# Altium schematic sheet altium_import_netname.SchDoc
size A4
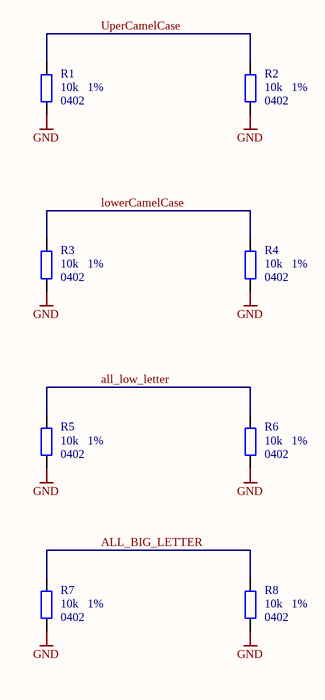
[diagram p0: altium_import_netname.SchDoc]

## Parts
R1  tolerance: 1%  package: 0402  [CRCW0402]  (hidden comment: 10k)
R2  tolerance: 1%  package: 0402  [CRCW0402]  (hidden comment: 10k)
R3  tolerance: 1%  package: 0402  [CRCW0402]  (hidden comment: 10k)
R4  tolerance: 1%  package: 0402  [CRCW0402]  (hidden comment: 10k)
R5  tolerance: 1%  package: 0402  [CRCW0402]  (hidden comment: 10k)
R6  tolerance: 1%  package: 0402  [CRCW0402]  (hidden comment: 10k)
R7  tolerance: 1%  package: 0402  [CRCW0402]  (hidden comment: 10k)
R8  tolerance: 1%  package: 0402  [CRCW0402]  (hidden comment: 10k)

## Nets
GND: R1.1 R2.1 R3.1 R4.1 R5.1 R6.1 R7.1 R8.1
ALL_BIG_LETTER: R7.2 R8.2
all_low_letter: R5.2 R6.2
lowerCamelCase: R3.2 R4.2
UperCamelCase: R1.2 R2.2

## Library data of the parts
R1-R8 = CRCW040210K0FKED: 0.063W, 0402, 1%, 10k, 50 V; Manufacturer: Vishay; voltage: 50 V; Certification: AEC-Q200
